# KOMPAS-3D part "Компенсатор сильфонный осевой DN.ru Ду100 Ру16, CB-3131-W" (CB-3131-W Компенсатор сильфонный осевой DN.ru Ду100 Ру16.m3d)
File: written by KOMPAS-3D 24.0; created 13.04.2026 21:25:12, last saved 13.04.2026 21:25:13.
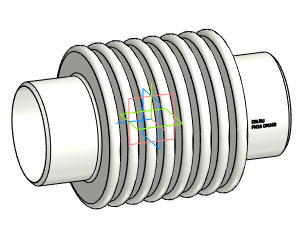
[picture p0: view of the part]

Document properties: Автор: DN.RU; Полное имя файла: D:\PROJECT CAD\DN.RU\...197(ACTUALE). CB-3131-W Компенсатор сильфонный осевой DN.ru\Исходники\DN100\CB-3131-W Компенсатор сильфонный осевой DN.ru Ду100 Ру16.m3d

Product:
- Body: Твердое тело1  | qty 1
    Масса: 3.262984
- Part/product: Компенсатор сильфонный осевой DN.ru Ду100 Ру16  | designation CB-3131-W
    Масса: 2.5
    Раздел спецификации: Прочие изделия
    Комментарий: D140-02124
    Примечание: D140-02124
    additional columns: Типовые

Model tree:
1. Твердое тело1  (labels: Твердое тело1)

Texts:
  CB-3131-W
